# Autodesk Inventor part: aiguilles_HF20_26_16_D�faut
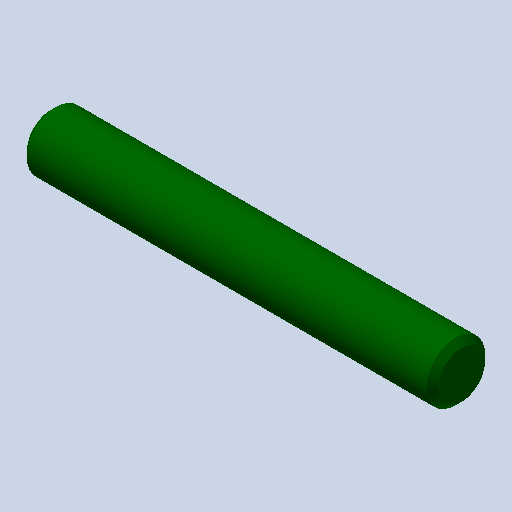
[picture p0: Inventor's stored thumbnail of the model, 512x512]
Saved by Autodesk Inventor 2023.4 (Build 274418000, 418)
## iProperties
Created: 2011-01
Part Number: aiguilles_HF20_26_16_D�faut
Document SubType Name: Modeling
Designer: eric
Density: 1 g/cm^3
Mass: 0.0437477 g
Surface Area: 0.926714 cm^2
Volume: 0.0437477 cm^3
Material: Générique
Appearance: 0,128,0_1
Author: eric
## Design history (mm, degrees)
feature "Base1"
node "Corps solides"
node "Corps surfaciques"
node "Solide1"
